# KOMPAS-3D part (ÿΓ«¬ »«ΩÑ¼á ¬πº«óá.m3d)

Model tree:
1. Эскиз:1
2. Операция выдавливания:1
     Расстояние 1 = 107.5
3. Эскиз:2
4. Операция выдавливания:2
     Расстояние 1 = 1.5
5. Эскиз:3
6. Операция выдавливания:3
     Расстояние 1 = 5; Расстояние 2 = 5
7. Эскиз:4
8. Вырезать элемент вращения:1
     Угол 1 = 360
9. Фаска:1
     Угол = 45; Длина 1 = 1; Длина 2 = 1
10. Эскиз:5
11. Вырезать элемент выдавливания:1
     Расстояние 2 = 9.5; Расстояние 1 = 20
12. Фаска:2
     Угол = 45; Длина 1 = 2; Длина 2 = 2
13. Фаска:3
     Угол = 45; Длина 1 = 0.75; Длина 2 = 0.75
14. Скругление:1
     Радиус = 0.5
